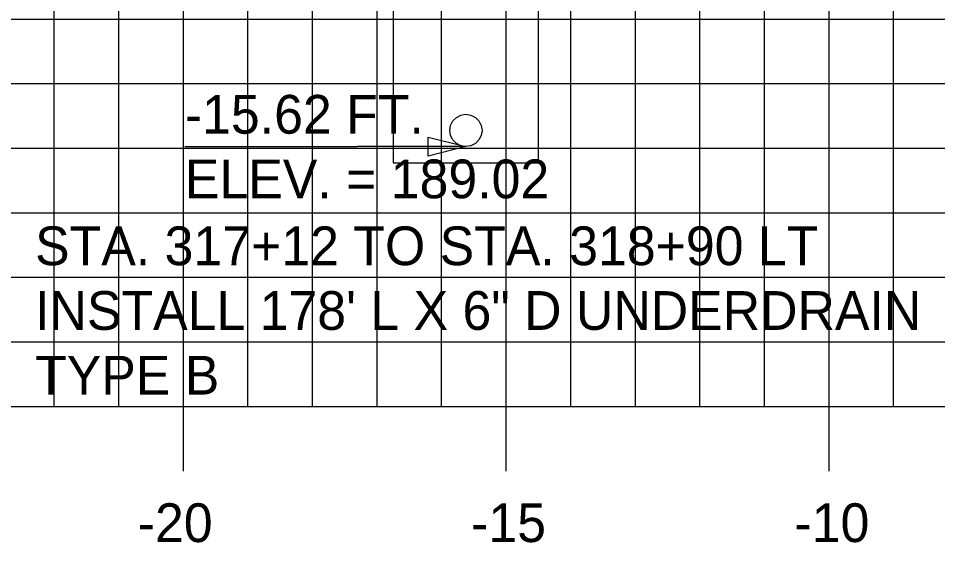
# Model space of a CAD drawing. Extents: x 1138985 to 1139155, y 608981 to 609091.
# Drawn here: x 1139045.39 to 1139059.63, y 609048.23 to 609056.34 of the extents above; entities that cross this region are included whole.
import ezdxf

# ---------------------------------------------------------------- set-up
doc = ezdxf.new("R2010")
doc.units = 0
for name, color, linetype in [('ANNOTATION', 7, 'Continuous'), ('D_Drainage_Underdrain', 7, 'Continuous'), ('D_Drainage_Underdrain_06in', 7, 'Continuous'), ('D_Text_Standard', 7, 'Continuous'), ('H_V ANNOTATION', 7, 'Continuous'), ('MAJOR', 7, 'Continuous'), ('MINOR', 7, 'Continuous')]:
    doc.layers.add(name, color=color, linetype=linetype)

msp = doc.modelspace()

# ---------------------------------------------------------------- linework, layer by layer
at = {"layer": 'D_Drainage_Underdrain'}
msp.add_lwpolyline([(1139051.199, 609057.474), (1139051.199, 609054.109), (1139053.449, 609054.109), (1139053.449, 609057.519)], close=True, dxfattribs=at)
at = {"layer": 'D_Drainage_Underdrain_06in'}
msp.add_lwpolyline([(1139052.324, 609054.859), (1139052.402, 609054.846), (1139052.471, 609054.811), (1139052.527, 609054.756), (1139052.562, 609054.686), (1139052.574, 609054.609), (1139052.562, 609054.531), (1139052.527, 609054.462), (1139052.471, 609054.406), (1139052.402, 609054.371), (1139052.324, 609054.359), (1139052.247, 609054.371), (1139052.177, 609054.406), (1139052.122, 609054.462), (1139052.087, 609054.531), (1139052.074, 609054.609), (1139052.087, 609054.686), (1139052.122, 609054.756), (1139052.177, 609054.811), (1139052.247, 609054.846)], close=True, dxfattribs=at)
at = {"layer": 'D_Text_Standard'}
msp.add_line((1139047.972, 609054.359), (1139050.647, 609054.359), dxfattribs=at)
msp.add_lwpolyline([(1139052.324, 609054.359), (1139051.742, 609054.213), (1139051.742, 609054.504)], close=True, dxfattribs=at)
msp.add_lwpolyline([(1139052.324, 609054.359), (1139051.327, 609054.359), (1139050.647, 609054.359)], dxfattribs=at)
at = {"layer": 'MAJOR'}
for p, q in [((1139047.949, 609050.335), (1139047.949, 609070.335)), ((1139052.949, 609050.335), (1139052.949, 609070.335)), ((1139057.949, 609050.335), (1139057.949, 609070.335)), ((1138997.949, 609055.335), (1139137.949, 609055.335)), ((1138997.949, 609050.335), (1139137.949, 609050.335)), ((1138997.949, 609050.335), (1139137.949, 609050.335)), ((1139047.949, 609049.333), (1139047.949, 609050.335)), ((1139052.949, 609049.333), (1139052.949, 609050.335)), ((1139057.949, 609049.333), (1139057.949, 609050.335))]:
    msp.add_line(p, q, dxfattribs=at)
at = {"layer": 'MINOR'}
for p, q in [((1139045.949, 609050.335), (1139045.949, 609070.335)), ((1139046.949, 609050.335), (1139046.949, 609070.335)), ((1139048.949, 609050.335), (1139048.949, 609070.335)), ((1139049.949, 609050.335), (1139049.949, 609070.335)), ((1139050.949, 609050.335), (1139050.949, 609070.335)), ((1139051.949, 609050.335), (1139051.949, 609070.335)), ((1139053.949, 609050.335), (1139053.949, 609070.335)), ((1139054.949, 609050.335), (1139054.949, 609070.335)), ((1139055.949, 609050.335), (1139055.949, 609070.335)), ((1139056.949, 609050.335), (1139056.949, 609070.335)), ((1139058.949, 609050.335), (1139058.949, 609070.335)), ((1138997.949, 609056.335), (1139137.949, 609056.335)), ((1138997.949, 609054.335), (1139137.949, 609054.335)), ((1138997.949, 609053.335), (1139137.949, 609053.335)), ((1138997.949, 609052.335), (1139137.949, 609052.335)), ((1138997.949, 609051.335), (1139137.949, 609051.335))]:
    msp.add_line(p, q, dxfattribs=at)

# ---------------------------------------------------------------- texts
at = {"layer": 'ANNOTATION'}
for s, p in [('STA. 317+12 TO STA. 318+90 LT', (1139045.652, 609052.523)), ('INSTALL 178\' L X 6" D UNDERDRAIN', (1139045.652, 609051.521)), ('TYPE B', (1139045.652, 609050.519))]:
    msp.add_text(s, height=0.6, dxfattribs=at).set_placement(p)
at = {"layer": 'D_Text_Standard'}
for s, p in [('-15.62 FT.', (1139047.972, 609054.559)), ('ELEV. = 189.02', (1139047.972, 609053.559))]:
    msp.add_text(s, height=0.6, dxfattribs=at).set_placement(p)
at = {"layer": 'H_V ANNOTATION'}
for s, p in [('-20', (1139047.242, 609048.235)), ('-15', (1139052.406, 609048.235)), ('-10', (1139057.414, 609048.235))]:
    msp.add_text(s, height=0.6, dxfattribs=at).set_placement(p)

doc.saveas('drawing.dxf')
